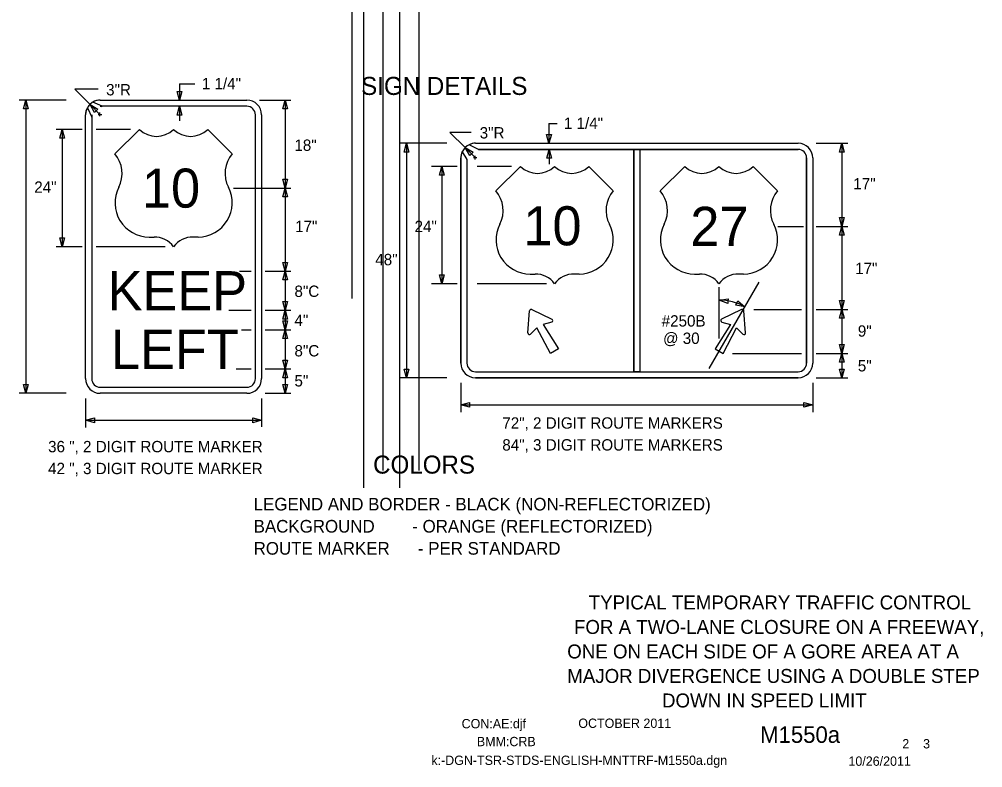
# Model space of a CAD drawing. Extents: x 16452 to 19508, y 5713 to 7079.
# Drawn here: x 17826 to 18466, y 5932 to 6430 of the extents above; entities that cross this region are included whole.
import ezdxf

# ---------------------------------------------------------------- set-up
doc = ezdxf.new("R2010")
doc.units = 0
for name, color, linetype in [('ALI_LEGAL_EX', 7, 'Continuous'), ('BORDER', 7, 'Continuous'), ('BORDER_SIGNAL_WO', 7, 'Continuous'), ('TRAFFIC_SIGNS_PR', 7, 'Continuous'), ('TYPICAL_EX', 7, 'Continuous'), ('TYPICAL_TEXT_DIMEN_PR', 7, 'Continuous')]:
    doc.layers.add(name, color=color, linetype=linetype)

msp = doc.modelspace()

# ---------------------------------------------------------------- linework, layer by layer
at = {"layer": 'ALI_LEGAL_EX'}
for p, q in [((18054.48, 7078.99), (18054.48, 6260.86)), ((18078.48, 7078.99), (18078.48, 6260.86)), ((18054.48, 6981.91), (18054.48, 6118)), ((18078.48, 6981.91), (18078.48, 6118)), ((18046.81, 6243.91), (18046.81, 6744.25)), ((18067.45, 6129.67), (18067.45, 6630.02)), ((18091.45, 6129.67), (18091.45, 6630.02))]:
    msp.add_line(p, q, dxfattribs=at)
at = {"layer": 'TRAFFIC_SIGNS_PR'}
for p, q in [((17879.4, 6375.92), (17976.9, 6375.92)), ((17871.82, 6372.3), (17870.82, 6370.79)), ((17870.84, 6370.72), (17873.72, 6364.68)), ((17880.61, 6371.86), (17874.51, 6374.6)), ((17976.9, 6371.86), (17879.4, 6371.86)), ((17869.65, 6190.67), (17869.65, 6366.17)), ((17873.72, 6366.17), (17873.72, 6190.67)), ((17982.59, 6190.67), (17982.59, 6366.17)), ((17986.65, 6366.17), (17986.65, 6190.67)), ((18130.88, 6343.17), (18124.65, 6346.19)), ((18128.92, 6347.22), (18343.42, 6347.22)), ((18128.92, 6347.22), (18343.42, 6347.22)), ((18130.86, 6343.16), (18234.14, 6343.16)), ((18343.42, 6343.16), (18130.86, 6343.16)), ((18234.14, 6343.16), (18234.14, 6195.28)), ((18238.21, 6343.16), (18238.21, 6195.28)), ((18238.21, 6343.16), (18343.42, 6343.16)), ((18119.17, 6337.47), (18119.17, 6200.97)), ((18119.17, 6200.97), (18119.17, 6337.47)), ((18120.09, 6341.48), (18123.23, 6336.44)), ((18349.11, 6337.47), (18349.11, 6291.72)), ((18349.11, 6200.97), (18349.11, 6337.47)), ((18353.17, 6337.47), (18353.17, 6200.97)), ((18353.17, 6337.47), (18353.17, 6200.97)), ((18123.24, 6336.42), (18123.24, 6200.97)), ((18123.24, 6336.42), (18123.24, 6200.97)), ((18349.11, 6291.72), (18349.11, 6200.97)), ((18163.78, 6221.08), (18164.93, 6235.8)), ((18166.44, 6236.67), (18179.75, 6230.31)), ((18305.91, 6236.67), (18292.59, 6230.31)), ((18308.57, 6221.08), (18307.42, 6235.8)), ((18128.92, 6195.28), (18343.42, 6195.28)), ((18128.92, 6191.22), (18343.42, 6191.22)), ((18343.42, 6191.22), (18128.92, 6191.22)), ((17879.4, 6184.98), (17976.9, 6184.98)), ((17976.9, 6180.92), (17879.4, 6180.92))]:
    msp.add_line(p, q, dxfattribs=at)
for points in [[(18130.86, 6343.16), (18130.85, 6343.16)], [(18123.23, 6336.44), (18123.24, 6336.42)], [(18179.59, 6228.34), (18173.87, 6226.76), (18184.09, 6210.59), (18178.69, 6207.47), (18169.79, 6224.41), (18165.57, 6220.24)], [(18292.76, 6228.34), (18298.48, 6226.76), (18288.26, 6210.59), (18293.66, 6207.47), (18302.56, 6224.41), (18306.78, 6220.24)]]:
    msp.add_lwpolyline(points, dxfattribs=at)
msp.add_lwpolyline([(18234.14, 6343.16), (18238.21, 6343.16), (18238.21, 6195.28), (18234.14, 6195.28)], close=True, dxfattribs=at)
for centre, radius, start, end in [((17879.4, 6366.17), 9.75, 90, 180), ((17878.82, 6368.34), 7.6, 85.58319, 124.53531), ((17976.9, 6366.17), 9.75, 0, 90), ((17876.69, 6366.76), 7.06, 145.86811, 184.82317), ((17880.01, 6376.28), 4.47, 262.2432, 277.7568), ((17976.9, 6366.17), 5.69, 0, 90), ((17868.26, 6365.43), 5.51, 352.24294, 7.75653), ((18128.92, 6337.47), 9.75, 90, 180), ((18128.92, 6337.47), 9.75, 90, 180), ((18128.25, 6340.65), 6.6, 84.11162, 123.06374), ((18129.86, 6350.34), 7.24, 277.81035, 278.05403), ((18343.42, 6337.47), 9.75, 0, 90), ((18343.42, 6337.47), 9.75, 0, 90), ((18343.42, 6337.47), 5.69, 0, 89.99421), ((18343.42, 6337.47), 5.69, 0, 90), ((18125.3, 6338.18), 6.17, 147.60925, 186.56283), ((18165.98, 6235.71), 1.06, 64.48226, 175.51774), ((18306.37, 6235.71), 1.06, 4.48226, 115.51774), ((18179.3, 6229.35), 1.06, 285.9885, 64.48226), ((18293.05, 6229.35), 1.06, 115.51774, 254.0115), ((18164.83, 6221), 1.06, 175.51775, 314.01151), ((18307.52, 6221), 1.06, 225.98849, 4.48225), ((18128.92, 6200.97), 9.75, 180, 270), ((18128.92, 6200.97), 9.75, 180, 270), ((18128.92, 6200.97), 5.69, 180, 270), ((18128.92, 6200.97), 5.69, 180, 270), ((18343.42, 6200.97), 9.75, 270, 0), ((18343.42, 6200.97), 5.69, 270, 0), ((18343.42, 6200.97), 9.75, 270, 0), ((18343.42, 6200.97), 5.69, 270, 0), ((17879.4, 6190.67), 9.75, 180, 270), ((17879.4, 6190.67), 5.69, 180, 270), ((17976.9, 6190.67), 5.69, 270, 0), ((17976.9, 6190.67), 9.75, 270, 0)]:
    msp.add_arc(centre, radius, start, end, dxfattribs=at)
at = {"layer": 'TYPICAL_EX'}
for p, q in [((17889.15, 6340.17), (17905.4, 6356.42)), ((17967.16, 6340.17), (17950.9, 6356.42)), ((18142.53, 6315.56), (18158.78, 6331.81)), ((18220.54, 6315.56), (18204.28, 6331.81)), ((18251.81, 6315.56), (18268.06, 6331.81)), ((18329.82, 6315.56), (18313.56, 6331.81)), ((17911.88, 6284.88), (17915.13, 6284.88)), ((17944.42, 6284.88), (17941.17, 6284.88)), ((18165.26, 6260.27), (18168.51, 6260.27)), ((18197.81, 6260.27), (18194.56, 6260.27)), ((18274.54, 6260.27), (18277.79, 6260.27)), ((18307.09, 6260.27), (18303.84, 6260.27))]:
    msp.add_line(p, q, dxfattribs=at)
for centre, radius, start, end in [((17916.78, 6368.26), 16.42, 226.14041, 313.85958), ((17939.53, 6368.26), 16.42, 226.14042, 313.85959), ((17873.75, 6327.16), 20.16, 333.09768, 40.19361), ((17982.55, 6327.16), 20.16, 139.80639, 206.90233), ((18170.16, 6343.65), 16.42, 226.14041, 313.85958), ((18192.91, 6343.65), 16.42, 226.14042, 313.85959), ((18279.44, 6343.65), 16.42, 226.14041, 313.85958), ((18302.19, 6343.65), 16.42, 226.14042, 313.85959), ((17911.92, 6307.6), 22.73, 152.6698, 269.90132), ((17944.38, 6307.6), 22.73, 270.09868, 27.3302), ((18127.13, 6302.55), 20.16, 333.09768, 40.19361), ((18235.94, 6302.55), 20.16, 139.80639, 206.90233), ((18236.41, 6302.55), 20.16, 333.09768, 40.19361), ((18345.21, 6302.55), 20.16, 139.80639, 206.90233), ((18165.3, 6282.99), 22.73, 152.6698, 269.90132), ((18197.77, 6282.99), 22.73, 270.09868, 27.3302), ((18274.58, 6282.99), 22.73, 152.6698, 269.90132), ((18307.05, 6282.99), 22.73, 270.09868, 27.3302), ((17915.17, 6268.6), 16.28, 37.1038, 90.13853), ((17941.13, 6268.6), 16.28, 89.86147, 142.8962), ((18168.55, 6243.99), 16.28, 37.1038, 90.13853), ((18194.52, 6243.99), 16.28, 89.86147, 142.8962), ((18277.83, 6243.99), 16.28, 37.1038, 90.13853), ((18303.8, 6243.99), 16.28, 89.86147, 142.8962)]:
    msp.add_arc(centre, radius, start, end, dxfattribs=at)
at = {"layer": 'TYPICAL_TEXT_DIMEN_PR'}
for p, q in [((17878.02, 6383.2), (17862.37, 6383.2)), ((17862.37, 6383.2), (17872.6, 6372.97)), ((17932.12, 6375.92), (17930.55, 6381.78)), ((17930.55, 6381.78), (17932.12, 6381.78)), ((17932.12, 6386.68), (17932.12, 6375.92)), ((17932.12, 6386.68), (17942.23, 6386.68)), ((17932.12, 6381.78), (17933.69, 6381.78)), ((17933.69, 6381.78), (17932.12, 6375.92)), ((17856.82, 6375.92), (17825.53, 6375.92)), ((17828.3, 6370.06), (17829.87, 6375.92)), ((17829.87, 6375.92), (17829.87, 6180.92)), ((17829.87, 6375.92), (17831.44, 6370.06)), ((17985.19, 6375.92), (18006.15, 6375.92)), ((18000.69, 6370.06), (18002.26, 6375.92)), ((18002.26, 6375.92), (18002.26, 6317.42)), ((18002.26, 6375.92), (18003.83, 6370.06)), ((17829.87, 6370.06), (17828.3, 6370.06)), ((17831.44, 6370.06), (17829.87, 6370.06)), ((17872.6, 6372.97), (17879.16, 6366.41)), ((17875.64, 6367.71), (17872.6, 6372.97)), ((17872.6, 6372.97), (17877.86, 6369.93)), ((17876.75, 6368.82), (17875.64, 6367.71)), ((17877.86, 6369.93), (17876.75, 6368.82)), ((17930.6, 6365.99), (17932.17, 6371.86)), ((17932.17, 6371.86), (17932.17, 6362.11)), ((17932.17, 6371.86), (17933.74, 6365.99)), ((18002.26, 6370.06), (18000.69, 6370.06)), ((18003.83, 6370.06), (18002.26, 6370.06)), ((17877.95, 6366.41), (17880.37, 6366.41)), ((17879.16, 6365.2), (17879.16, 6367.62)), ((17932.17, 6365.99), (17930.6, 6365.99)), ((17933.74, 6365.99), (17932.17, 6365.99)), ((17867.28, 6356.42), (17850.15, 6356.42)), ((17852.48, 6350.56), (17854.05, 6356.42)), ((17854.05, 6356.42), (17854.05, 6278.42)), ((17854.05, 6356.42), (17855.62, 6350.56)), ((17899.52, 6356.42), (17876.64, 6356.42)), ((18177.78, 6360.37), (18177.78, 6347.22)), ((18177.78, 6360.37), (18183.31, 6360.37)), ((17854.05, 6350.56), (17852.48, 6350.56)), ((17855.62, 6350.56), (17854.05, 6350.56)), ((18126.06, 6354.5), (18111.89, 6354.5)), ((18111.89, 6354.5), (18122.04, 6344.36)), ((18177.78, 6347.22), (18176.21, 6353.08)), ((18176.21, 6353.08), (18177.78, 6353.08)), ((18177.78, 6353.08), (18179.35, 6353.08)), ((18179.35, 6353.08), (18177.78, 6347.22)), ((18109.94, 6347.22), (18078.65, 6347.22)), ((18081.42, 6341.36), (18082.99, 6347.22)), ((18082.99, 6347.22), (18082.99, 6191.22)), ((18082.99, 6347.22), (18084.56, 6341.36)), ((18122.04, 6344.36), (18128.68, 6337.71)), ((18125.07, 6339.1), (18122.04, 6344.36)), ((18122.04, 6344.36), (18127.29, 6341.32)), ((18176.26, 6337.3), (18177.83, 6343.16)), ((18176.26, 6337.3), (18177.83, 6343.16)), ((18177.83, 6343.16), (18177.83, 6333.41)), ((18177.83, 6343.16), (18179.4, 6337.3)), ((18177.83, 6343.16), (18179.4, 6337.3)), ((18355.55, 6347.22), (18376.51, 6347.22)), ((18371.04, 6341.36), (18372.61, 6347.22)), ((18372.61, 6347.22), (18372.61, 6291.97)), ((18372.61, 6347.22), (18374.18, 6341.36)), ((18082.99, 6341.36), (18081.42, 6341.36)), ((18084.56, 6341.36), (18082.99, 6341.36)), ((18126.18, 6340.21), (18125.07, 6339.1)), ((18127.29, 6341.32), (18126.18, 6340.21)), ((18127.48, 6337.71), (18129.89, 6337.71)), ((18128.68, 6336.5), (18128.68, 6338.92)), ((18177.83, 6337.3), (18176.26, 6337.3)), ((18177.83, 6337.3), (18176.26, 6337.3)), ((18179.4, 6337.3), (18177.83, 6337.3)), ((18179.4, 6337.3), (18177.83, 6337.3)), ((18372.61, 6341.36), (18371.04, 6341.36)), ((18374.18, 6341.36), (18372.61, 6341.36)), ((18116.8, 6331.81), (18099.67, 6331.81)), ((18104.97, 6325.95), (18106.54, 6331.81)), ((18106.54, 6331.81), (18106.54, 6253.81)), ((18106.54, 6331.81), (18108.11, 6325.95)), ((18152.9, 6331.81), (18130.03, 6331.81)), ((18106.54, 6325.95), (18104.97, 6325.95)), ((18108.11, 6325.95), (18106.54, 6325.95)), ((17968.04, 6317.42), (18006.15, 6317.42)), ((18002.26, 6317.42), (18000.69, 6323.28)), ((18000.69, 6323.28), (18002.26, 6323.28)), ((18000.69, 6311.56), (18002.26, 6317.42)), ((18002.26, 6323.28), (18003.83, 6323.28)), ((18003.83, 6323.28), (18002.26, 6317.42)), ((18002.26, 6317.42), (18002.26, 6262.17)), ((18002.26, 6317.42), (18003.83, 6311.56)), ((18002.26, 6311.56), (18000.69, 6311.56)), ((18003.83, 6311.56), (18002.26, 6311.56)), ((18329.99, 6291.97), (18347.14, 6291.97)), ((18355.55, 6291.97), (18376.51, 6291.97)), ((18372.61, 6291.97), (18371.04, 6297.83)), ((18371.04, 6297.83), (18372.61, 6297.83)), ((18371.04, 6286.11), (18372.61, 6291.97)), ((18372.61, 6297.83), (18374.18, 6297.83)), ((18374.18, 6297.83), (18372.61, 6291.97)), ((18372.61, 6291.97), (18372.61, 6236.72)), ((18372.61, 6291.97), (18374.18, 6286.11)), ((18372.61, 6286.11), (18371.04, 6286.11)), ((18374.18, 6286.11), (18372.61, 6286.11)), ((17854.05, 6278.42), (17852.48, 6284.28)), ((17852.48, 6284.28), (17854.05, 6284.28)), ((17854.05, 6284.28), (17855.62, 6284.28)), ((17855.62, 6284.28), (17854.05, 6278.42)), ((17867.28, 6278.42), (17850.15, 6278.42)), ((17922.64, 6278.42), (17876.64, 6278.42)), ((18002.26, 6262.17), (18000.69, 6268.03)), ((18000.69, 6268.03), (18002.26, 6268.03)), ((18002.26, 6268.03), (18003.83, 6268.03)), ((18003.83, 6268.03), (18002.26, 6262.17)), ((17971.98, 6262.17), (17979.66, 6262.17)), ((17989.03, 6262.17), (18006.15, 6262.17)), ((18000.69, 6256.31), (18002.26, 6262.17)), ((18002.26, 6262.17), (18002.26, 6236.17)), ((18002.26, 6262.17), (18003.83, 6256.31)), ((18106.54, 6253.81), (18104.97, 6259.67)), ((18104.97, 6259.67), (18106.54, 6259.67)), ((18106.54, 6259.67), (18108.11, 6259.67)), ((18108.11, 6259.67), (18106.54, 6253.81)), ((18002.26, 6256.31), (18000.69, 6256.31)), ((18003.83, 6256.31), (18002.26, 6256.31)), ((18116.8, 6253.81), (18099.67, 6253.81)), ((18176.03, 6253.81), (18130.03, 6253.81)), ((18284.21, 6197.32), (18317.45, 6254.91)), ((18290.96, 6217.48), (18290.96, 6251.47)), ((18002.26, 6236.17), (18000.69, 6242.03)), ((18000.69, 6242.03), (18002.26, 6242.03)), ((18002.26, 6242.03), (18003.83, 6242.03)), ((18003.83, 6242.03), (18002.26, 6236.17)), ((18290.99, 6242.91), (18296.98, 6243.87)), ((18296.66, 6240.75), (18290.99, 6242.91)), ((18296.82, 6242.31), (18296.66, 6240.75)), ((18296.98, 6243.87), (18296.82, 6242.31)), ((18301.98, 6239.59), (18302.66, 6241.01)), ((18302.66, 6241.01), (18303.34, 6242.42)), ((18303.34, 6242.42), (18307.94, 6238.46)), ((18372.61, 6236.72), (18371.04, 6242.58)), ((18371.04, 6242.58), (18372.61, 6242.58)), ((18372.61, 6242.58), (18374.18, 6242.58)), ((18374.18, 6242.58), (18372.61, 6236.72)), ((17964.96, 6236.17), (17979.66, 6236.17)), ((17989.03, 6236.17), (18006.15, 6236.17)), ((18000.69, 6230.31), (18002.26, 6236.17)), ((18002.26, 6236.17), (18002.26, 6223.17)), ((18002.26, 6236.17), (18003.83, 6230.31)), ((18307.94, 6238.46), (18301.98, 6239.59)), ((18313.91, 6236.72), (18345.78, 6236.72)), ((18355.55, 6236.72), (18376.51, 6236.72)), ((18371.04, 6230.86), (18372.61, 6236.72)), ((18372.61, 6236.72), (18372.61, 6207.47)), ((18372.61, 6236.72), (18374.18, 6230.86)), ((18002.26, 6230.31), (18000.69, 6230.31)), ((18002.26, 6223.17), (18000.69, 6229.03)), ((18000.69, 6229.03), (18002.26, 6229.03)), ((18003.83, 6230.31), (18002.26, 6230.31)), ((18002.26, 6229.03), (18003.83, 6229.03)), ((18003.83, 6229.03), (18002.26, 6223.17)), ((18372.61, 6230.86), (18371.04, 6230.86)), ((18374.18, 6230.86), (18372.61, 6230.86)), ((17973.32, 6223.17), (17979.66, 6223.17)), ((17989.03, 6223.17), (18006.15, 6223.17)), ((18000.69, 6217.31), (18002.26, 6223.17)), ((18002.26, 6223.17), (18002.26, 6197.17)), ((18002.26, 6223.17), (18003.83, 6217.31)), ((18002.26, 6217.31), (18000.69, 6217.31)), ((18003.83, 6217.31), (18002.26, 6217.31)), ((18372.61, 6207.47), (18371.04, 6213.33)), ((18371.04, 6213.33), (18372.61, 6213.33)), ((18372.61, 6213.33), (18374.18, 6213.33)), ((18374.18, 6213.33), (18372.61, 6207.47)), ((18002.26, 6197.17), (18000.69, 6203.03)), ((18000.69, 6203.03), (18002.26, 6203.03)), ((18002.26, 6203.03), (18003.83, 6203.03)), ((18003.83, 6203.03), (18002.26, 6197.17)), ((18299.78, 6207.47), (18345.78, 6207.47)), ((18355.55, 6207.47), (18376.51, 6207.47)), ((18371.04, 6201.61), (18372.61, 6207.47)), ((18372.61, 6207.47), (18372.61, 6191.22)), ((18372.61, 6207.47), (18374.18, 6201.61)), ((17969.82, 6197.17), (17979.66, 6197.17)), ((17989.03, 6197.17), (18006.15, 6197.17)), ((18000.69, 6191.31), (18002.26, 6197.17)), ((18002.26, 6197.17), (18002.26, 6180.92)), ((18002.26, 6197.17), (18003.83, 6191.31)), ((18082.99, 6191.22), (18081.42, 6197.08)), ((18081.42, 6197.08), (18082.99, 6197.08)), ((18082.99, 6197.08), (18084.56, 6197.08)), ((18084.56, 6197.08), (18082.99, 6191.22)), ((18372.61, 6201.61), (18371.04, 6201.61)), ((18372.61, 6191.22), (18371.04, 6197.08)), ((18371.04, 6197.08), (18372.61, 6197.08)), ((18374.18, 6201.61), (18372.61, 6201.61)), ((18372.61, 6197.08), (18374.18, 6197.08)), ((18374.18, 6197.08), (18372.61, 6191.22)), ((18002.26, 6191.31), (18000.69, 6191.31)), ((18003.83, 6191.31), (18002.26, 6191.31)), ((18109.94, 6191.22), (18078.65, 6191.22)), ((18355.55, 6191.22), (18372.67, 6191.22)), ((18355.55, 6191.22), (18376.51, 6191.22)), ((18355.55, 6191.22), (18372.67, 6191.22)), ((17829.87, 6180.92), (17828.3, 6186.78)), ((17828.3, 6186.78), (17829.87, 6186.78)), ((17829.87, 6186.78), (17831.44, 6186.78)), ((17831.44, 6186.78), (17829.87, 6180.92)), ((18002.26, 6180.92), (18000.69, 6186.78)), ((18000.69, 6186.78), (18002.26, 6186.78)), ((18002.26, 6186.78), (18003.83, 6186.78)), ((18003.83, 6186.78), (18002.26, 6180.92)), ((18119.17, 6187.88), (18119.17, 6168.31)), ((18353.17, 6187.88), (18353.17, 6168.31)), ((17856.82, 6180.92), (17825.53, 6180.92)), ((17869.65, 6177.57), (17869.65, 6158.22)), ((17986.65, 6177.57), (17986.65, 6158.68)), ((17989.03, 6180.92), (18006.15, 6180.92)), ((18119.17, 6173.25), (18125.04, 6174.82)), ((18119.17, 6173.25), (18353.17, 6173.25)), ((18125.04, 6171.68), (18119.17, 6173.25)), ((18125.04, 6174.82), (18125.04, 6173.25)), ((18125.04, 6173.25), (18125.04, 6171.68)), ((18347.31, 6173.25), (18347.31, 6174.82)), ((18347.31, 6174.82), (18353.17, 6173.25)), ((18353.17, 6173.25), (18347.31, 6171.68)), ((18347.31, 6171.68), (18347.31, 6173.25)), ((17869.65, 6162.95), (17875.51, 6164.52)), ((17875.51, 6164.52), (17875.51, 6162.95)), ((17980.79, 6162.95), (17980.79, 6164.52)), ((17980.79, 6164.52), (17986.65, 6162.95)), ((17869.65, 6162.95), (17986.65, 6162.95)), ((17875.51, 6161.38), (17869.65, 6162.95)), ((17875.51, 6162.95), (17875.51, 6161.38)), ((17986.65, 6162.95), (17980.79, 6161.38)), ((17980.79, 6161.38), (17980.79, 6162.95))]:
    msp.add_line(p, q, dxfattribs=at)
msp.add_arc((18291.16, 6208.48), 34.39, 60.74521, 90.32117, dxfattribs=at)

# ---------------------------------------------------------------- texts
at = {"layer": 'BORDER'}
for s, p in [('TYPICAL TEMPORARY TRAFFIC CONTROL', (18204.21, 6037.14)), ('FOR A TWO-LANE CLOSURE ON A FREEWAY,', (18194.41, 6020.84)), ('ONE ON EACH SIDE OF A GORE AREA AT A ', (18189.92, 6004.54)), ('MAJOR DIVERGENCE USING A DOUBLE STEP ', (18189.92, 5988.24)), ('DOWN IN SPEED LIMIT', (18252.92, 5971.94))]:
    msp.add_text(s, height=9.3, dxfattribs=at).set_placement(p)
at = {"layer": 'BORDER_SIGNAL_WO'}
for s, height, p in [('CON:AE:djf  ', 6.2, (18119.69, 5958.06)), ('    OCTOBER 2011    ', 6.2, (18188.08, 5958.34)), ('    M1550a   ', 11, (18301.86, 5948.38)), ('BMM:CRB   ', 6.2, (18129.81, 5946.17)), (' 2    3 ', 6.2, (18410.45, 5944.7)), ('k:-DGN-TSR-STDS-ENGLISH-MNTTRF-M1550a.dgn      ', 6.2, (18099.55, 5933.71)), ('10/26/2011    ', 6.2, (18376.93, 5933.13))]:
    msp.add_text(s, height=height, dxfattribs=at).set_placement(p)
at = {"layer": 'TRAFFIC_SIGNS_PR'}
for s, p in [('10', (17907.12, 6304.42)), ('10', (18160.77, 6279.35)), ('27', (18271.78, 6278.99)), ('KEEP', (17884.26, 6236.17)), ('LEFT', (17886.49, 6197.17))]:
    msp.add_text(s, height=26, dxfattribs=at).set_placement(p)
at = {"layer": 'TYPICAL_TEXT_DIMEN_PR'}
for s, height, p in [('1 1/4"', 7.55, (17946.93, 6383.17)), ('SIGN DETAILS', 12, (18052.88, 6379.39)), ('3"R', 7.55, (17883.29, 6379.08)), ('1 1/4"', 7.55, (18187.71, 6356.8)), ('3"R', 7.55, (18131.71, 6350.43)), ('18"', 7.55, (18008.49, 6342.19)), ('17"', 7.55, (18380.18, 6316.58)), ('24"', 7.55, (17835.5, 6314.3)), ('17"', 7.55, (18008.95, 6288.14)), ('24"', 7.55, (18088.4, 6288.14)), ('48"', 7.55, (18062.29, 6266.12)), ('17"', 7.55, (18381.39, 6260.22)), ('8"C', 7.55, (18008.53, 6245.03)), ('4" ', 7.55, (18008.53, 6225.77)), ('#250B', 7.55, (18252.73, 6225.31)), ('@ 30', 7.55, (18253.68, 6213.76)), ('9"', 7.55, (18383.17, 6218.57)), ('8"C', 7.55, (18008.53, 6205.44)), ('5"', 7.55, (18383.16, 6195.47)), ('5" ', 7.55, (18008.53, 6185.46)), ('72", 2 DIGIT ROUTE MARKERS', 7.55, (18146.75, 6157.39)), ('36 ", 2 DIGIT ROUTE MARKER', 7.55, (17844.7, 6141.69)), ('84", 3 DIGIT ROUTE MARKERS', 7.55, (18146.75, 6142.84)), ('COLORS', 12, (18060.82, 6127.5)), ('42 ", 3 DIGIT ROUTE MARKER', 7.55, (17844.7, 6127.14)), ('LEGEND AND BORDER - BLACK (NON-REFLECTORIZED)', 8.4, (17981.39, 6102.97)), ('BACKGROUND        - ORANGE (REFLECTORIZED)', 8.4, (17981.39, 6088.27)), ('ROUTE MARKER      - PER STANDARD', 8.4, (17981.39, 6073.57))]:
    msp.add_text(s, height=height, dxfattribs=at).set_placement(p)

doc.saveas('drawing.dxf')
